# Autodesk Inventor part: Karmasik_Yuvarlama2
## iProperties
Created: 2009-12
Part Number: Karmasik_Yuvarlama2
Document SubType Name: Modeling
Designer: bulent
Density: 1 g/cm^3
Author: bulent
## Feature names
1. Extrusion1
2. FaceDraft1
